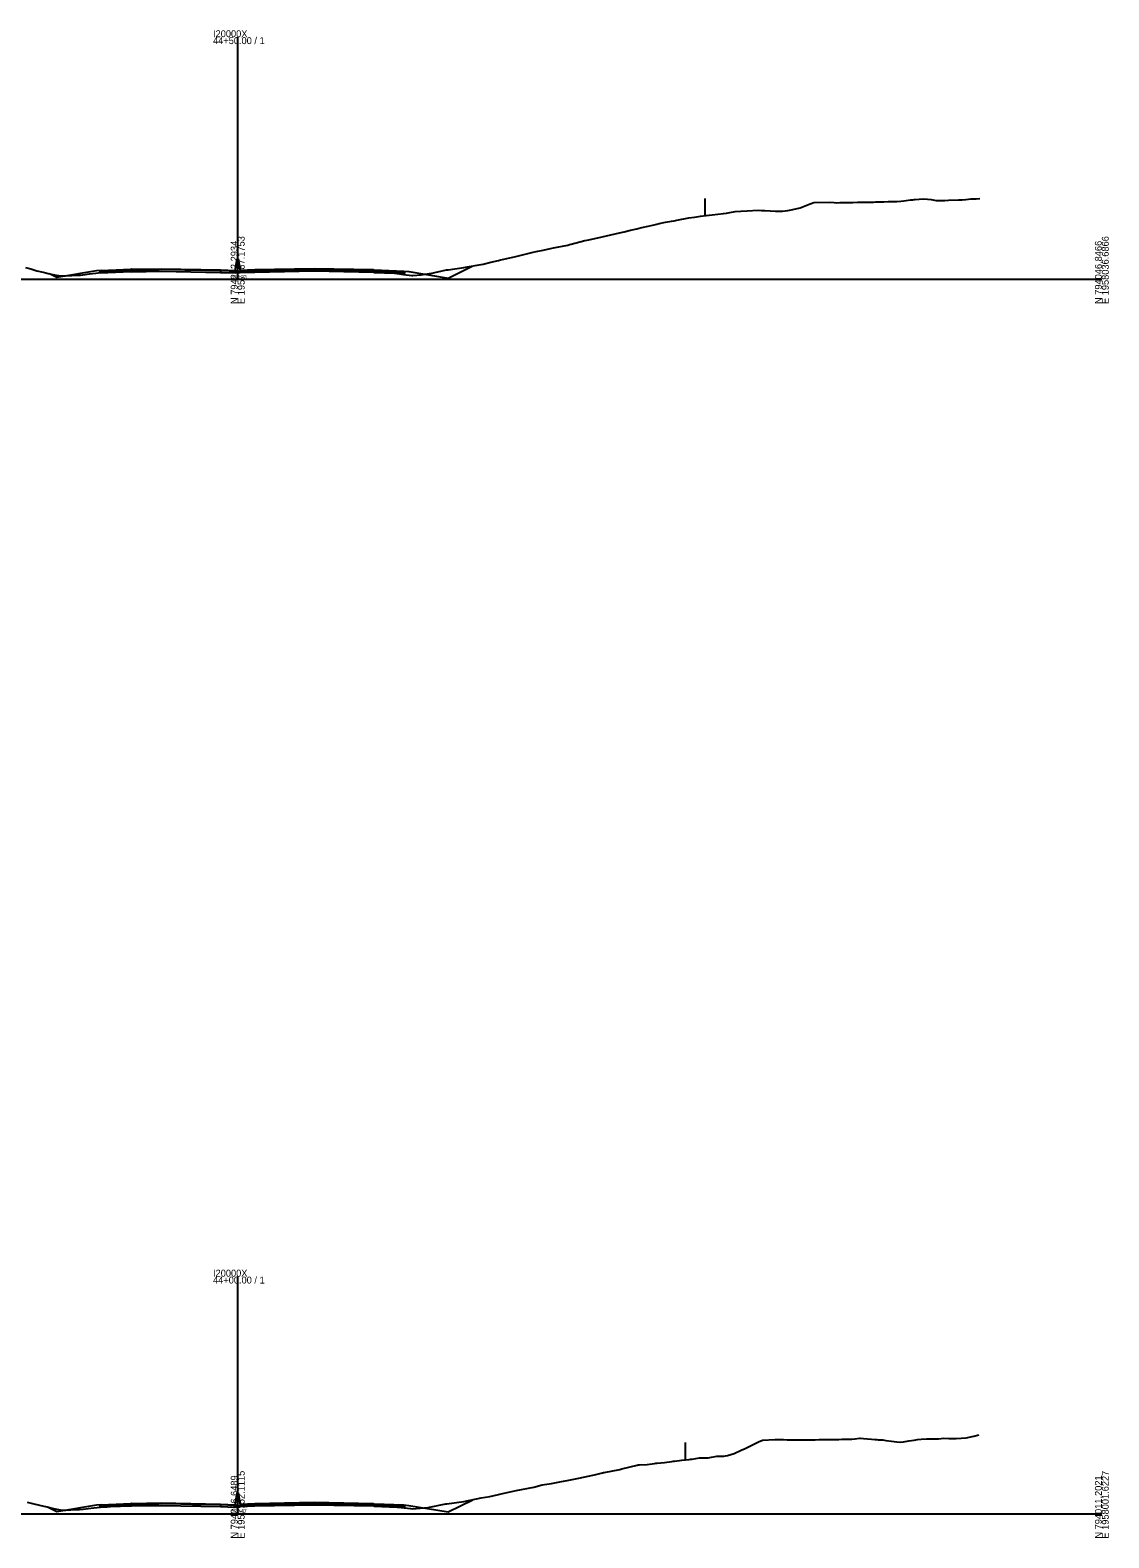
# Model space of a CAD drawing. Extents: x -4026 to 9638, y -10 to 19609.
# Drawn here: x -2734 to -2297, y 13990 to 14601 of the extents above; entities that cross this region are included whole.
import ezdxf

# ---------------------------------------------------------------- set-up
doc = ezdxf.new("R2010")
doc.units = 0
for name, color, linetype in [('RD_EX_Fence_Other', 7, 'Continuous'), ('RD_GPK_XS_Cell', 7, 'Continuous'), ('RD_XS_Base', 7, 'Continuous'), ('RD_XS_ExGround', 7, 'Continuous'), ('RD_XS_Greenside', 7, 'Continuous'), ('RD_XS_MedBWall', 7, 'Continuous'), ('RD_XS_Pave', 7, 'Continuous'), ('RD_XS_PaveOvlay', 7, 'Continuous'), ('RD_XS_TieSlope', 7, 'Continuous'), ('RD_XS_TX_Elev_EX', 7, 'Continuous')]:
    doc.layers.add(name, color=color, linetype=linetype)

msp = doc.modelspace()

# ---------------------------------------------------------------- linework, layer by layer
at = {"layer": 'RD_EX_Fence_Other'}
for p, q in [((-2460.82, 14532.74), (-2460.82, 14525.74)), ((-2468.7, 14028.93), (-2468.7, 14021.93))]:
    msp.add_line(p, q, dxfattribs=at)
at = {"layer": 'RD_GPK_XS_Cell'}
for p, q in [((-2650, 14500), (-2650, 14598.07)), ((-3000, 14500), (-2650, 14500)), ((-2650, 14500), (-2300, 14500)), ((-2650, 14000), (-2650, 14096.1)), ((-3000, 14000), (-2650, 14000)), ((-2650, 14000), (-2300, 14000))]:
    msp.add_line(p, q, dxfattribs=at)
at = {"layer": 'RD_XS_Base'}
for points in [[(-2705.75, 14503.21), (-2705.25, 14503.23), (-2693.25, 14503.71)], [(-2705.75, 14502.54), (-2705.75, 14503.21)], [(-2693.25, 14503.04), (-2705.75, 14502.54)], [(-2693.25, 14503.71), (-2693, 14503.71)], [(-2693.25, 14503.04), (-2693.25, 14503.71)], [(-2693, 14503.04), (-2693.25, 14503.04)], [(-2657, 14503.48), (-2681, 14503.96), (-2693, 14503.71)], [(-2693, 14503.71), (-2693, 14503.04)], [(-2693, 14503.04), (-2681, 14503.29), (-2657, 14502.81)], [(-2651, 14503.24), (-2657, 14503.48)], [(-2657, 14503.48), (-2657, 14502.81)], [(-2657, 14502.81), (-2651, 14502.57)], [(-2651, 14502.57), (-2651, 14503.24)], [(-2649, 14503.26), (-2643, 14503.5)], [(-2649, 14502.59), (-2649, 14503.26)], [(-2643, 14502.83), (-2649, 14502.59)], [(-2643, 14503.5), (-2619, 14503.98), (-2595, 14503.5)], [(-2643, 14502.83), (-2643, 14503.5)], [(-2595, 14502.83), (-2619, 14503.31), (-2643, 14502.83)], [(-2595, 14503.5), (-2594.75, 14503.49)], [(-2595, 14502.83), (-2595, 14503.5)], [(-2594.75, 14502.82), (-2595, 14502.83)], [(-2594.75, 14503.49), (-2594.75, 14502.82)], [(-2582.25, 14502.99), (-2582.75, 14503.01), (-2594.75, 14503.49)], [(-2594.75, 14502.82), (-2582.25, 14502.32)], [(-2582.25, 14502.32), (-2582.25, 14502.99)], [(-2705.75, 14003.38), (-2705.25, 14003.4), (-2693.25, 14003.87)], [(-2705.75, 14002.71), (-2705.75, 14003.38)], [(-2693.25, 14003.2), (-2705.75, 14002.71)], [(-2693.25, 14003.87), (-2693, 14003.88)], [(-2693.25, 14003.2), (-2693.25, 14003.87)], [(-2693, 14003.21), (-2693.25, 14003.2)], [(-2657, 14003.64), (-2681, 14004.12), (-2693, 14003.88)], [(-2693, 14003.88), (-2693, 14003.21)], [(-2693, 14003.21), (-2681, 14003.45), (-2657, 14002.97)], [(-2651, 14003.41), (-2657, 14003.64)], [(-2657, 14003.64), (-2657, 14002.97)], [(-2657, 14002.97), (-2651, 14002.74)], [(-2651, 14002.74), (-2651, 14003.41)], [(-2649, 14003.54), (-2643, 14003.78)], [(-2649, 14002.87), (-2649, 14003.54)], [(-2643, 14003.11), (-2649, 14002.87)], [(-2643, 14003.78), (-2619, 14004.27), (-2595, 14003.78)], [(-2643, 14003.11), (-2643, 14003.78)], [(-2595, 14003.11), (-2619, 14003.6), (-2643, 14003.11)], [(-2595, 14003.78), (-2594.75, 14003.78)], [(-2595, 14003.11), (-2595, 14003.78)], [(-2594.75, 14003.11), (-2595, 14003.11)], [(-2594.75, 14003.78), (-2594.75, 14003.11)], [(-2582.25, 14003.28), (-2582.75, 14003.3), (-2594.75, 14003.78)], [(-2594.75, 14003.11), (-2582.25, 14002.61)], [(-2582.25, 14002.61), (-2582.25, 14003.28)]]:
    msp.add_lwpolyline(points, dxfattribs=at)
at = {"layer": 'RD_XS_ExGround'}
for points in [[(-2735.92, 14504.85), (-2733.78, 14504.25), (-2731.31, 14503.46), (-2728.79, 14502.86), (-2727.77, 14502.61), (-2726.77, 14502.37), (-2724.24, 14501.77), (-2721.66, 14501.47), (-2719.75, 14501.39), (-2714.53, 14501.68), (-2713.63, 14501.75), (-2712.74, 14501.88), (-2710.09, 14502.25), (-2707.4, 14502.53), (-2706.56, 14502.61), (-2704.92, 14502.74), (-2704.35, 14502.79), (-2703.13, 14502.88), (-2699.16, 14503.22), (-2698.77, 14503.24), (-2690.11, 14503.73), (-2689.13, 14503.76), (-2687.92, 14503.81), (-2686.95, 14503.83), (-2686.16, 14503.85), (-2685.51, 14503.86), (-2685.01, 14503.89), (-2678.6, 14504.09), (-2671.98, 14503.92), (-2671.39, 14503.9), (-2670.68, 14503.89), (-2669.83, 14503.87), (-2668.77, 14503.84), (-2667.42, 14503.8), (-2666.86, 14503.79), (-2655.35, 14503.56), (-2649.81, 14503.21), (-2647.63, 14503.21), (-2645.79, 14503.2), (-2643.08, 14503.36), (-2640.65, 14503.5), (-2633.71, 14503.67), (-2628.93, 14503.78), (-2620.18, 14503.96), (-2617.16, 14504.02), (-2616.42, 14504), (-2605.56, 14503.77), (-2598.78, 14503.45), (-2597.14, 14503.38), (-2596.5, 14503.34), (-2589.88, 14502.98), (-2586.2, 14502.49), (-2582.81, 14501.94), (-2579.48, 14501.58), (-2579.07, 14501.58), (-2575.74, 14501.86), (-2572.46, 14502.31), (-2571.94, 14502.41), (-2565.45, 14503.82), (-2565.13, 14503.87), (-2564.81, 14503.9), (-2558.44, 14504.73), (-2557.68, 14504.89), (-2551.42, 14506.02), (-2550.55, 14506.18), (-2547.45, 14506.93), (-2544.41, 14507.69), (-2543.92, 14507.8), (-2543.42, 14507.9), (-2537.4, 14509.24), (-2536.29, 14509.52), (-2530.38, 14510.98), (-2529.16, 14511.25), (-2526.24, 14511.84), (-2523.37, 14512.52), (-2522.03, 14512.82), (-2516.35, 14513.9), (-2515.63, 14514.05), (-2514.9, 14514.25), (-2509.34, 14515.67), (-2507.77, 14516.02), (-2502.33, 14517.24), (-2500.64, 14517.65), (-2495.31, 14518.89), (-2493.51, 14519.28), (-2490.88, 14519.9), (-2488.3, 14520.48), (-2487.35, 14520.72), (-2486.38, 14520.93), (-2483.81, 14521.55), (-2481.29, 14522.09), (-2480.28, 14522.32), (-2479.25, 14522.56), (-2476.74, 14523.1), (-2474.27, 14523.52), (-2473.2, 14523.7), (-2472.12, 14523.94), (-2467.26, 14524.93), (-2464.99, 14525.24), (-2462.6, 14525.58), (-2460.24, 14525.79), (-2459.06, 14526.02), (-2457.86, 14526.11), (-2455.53, 14526.35), (-2453.23, 14526.65), (-2451.99, 14526.81), (-2450.73, 14527.1), (-2448.46, 14527.46), (-2446.22, 14527.56), (-2443.6, 14527.78), (-2439.2, 14528.05), (-2437.85, 14527.91), (-2436.47, 14527.84), (-2434.31, 14527.72), (-2432.19, 14527.67), (-2430.78, 14527.64), (-2429.34, 14527.65), (-2427.24, 14527.82), (-2425.18, 14528.23), (-2422.21, 14529.02), (-2418.16, 14530.52), (-2416.63, 14531.1), (-2410.26, 14531.3), (-2408.37, 14531.12), (-2407.53, 14531.04), (-2406.11, 14531.07), (-2405.71, 14531.07), (-2403.46, 14531.1), (-2402.32, 14531.12), (-2400.79, 14531.15), (-2398.9, 14531.19), (-2398.12, 14531.2), (-2395.29, 14531.23), (-2393.04, 14531.29), (-2392.5, 14531.31), (-2391.61, 14531.33), (-2389.54, 14531.39), (-2388.26, 14531.42), (-2386.57, 14531.46), (-2385.88, 14531.48), (-2383.48, 14531.54), (-2383.05, 14531.55), (-2381.45, 14531.7), (-2380.21, 14531.84), (-2379.19, 14531.95), (-2377.51, 14532.14), (-2376.61, 14532.23), (-2376.04, 14532.29), (-2375.66, 14532.32), (-2372.3, 14532.55), (-2370.67, 14532.51), (-2369.07, 14532.27), (-2367.13, 14531.99), (-2365.17, 14531.87), (-2363.6, 14531.89), (-2362.05, 14532.02), (-2358.04, 14532.16), (-2356.53, 14532.24), (-2355.04, 14532.29), (-2352.99, 14532.56), (-2350.91, 14532.54), (-2349.46, 14532.69)], [(-2735.25, 14004.73), (-2733.69, 14004.38), (-2729.71, 14003.42), (-2726.68, 14002.7), (-2724.65, 14002.22), (-2722.58, 14001.81), (-2721.11, 14001.5), (-2719.66, 14001.53), (-2717.58, 14001.59), (-2715.45, 14001.73), (-2714.04, 14001.83), (-2712.65, 14001.96), (-2710.5, 14002.17), (-2708.32, 14002.41), (-2706.97, 14002.55), (-2704.04, 14002.82), (-2702.9, 14002.92), (-2700.25, 14003.14), (-2699.27, 14003.23), (-2697.24, 14003.36), (-2690.25, 14003.8), (-2689.74, 14003.82), (-2688.4, 14003.86), (-2687.35, 14003.89), (-2686.5, 14003.93), (-2685.8, 14003.95), (-2685.22, 14003.96), (-2678.63, 14004.16), (-2672.3, 14004.07), (-2671.77, 14004.06), (-2671.14, 14004.04), (-2670.39, 14004.04), (-2669.47, 14004.02), (-2668.32, 14004), (-2666.83, 14003.98), (-2655.54, 14003.82), (-2651.54, 14003.56), (-2649.77, 14003.45), (-2648.46, 14003.49), (-2647.48, 14003.51), (-2645.76, 14003.55), (-2643.29, 14003.7), (-2641.58, 14003.79), (-2640.66, 14003.84), (-2629.94, 14004.1), (-2628.97, 14004.12), (-2627.08, 14004.15), (-2617.31, 14004.32), (-2607.02, 14004.14), (-2605.64, 14004.12), (-2604.53, 14004.07), (-2596.99, 14003.75), (-2596.39, 14003.74), (-2590.29, 14003.52), (-2587.12, 14003.02), (-2586.4, 14002.91), (-2579.99, 14002.14), (-2579.39, 14002.12), (-2572.86, 14002.6), (-2572.37, 14002.68), (-2565.73, 14004.03), (-2565.36, 14004.12), (-2558.35, 14005.01), (-2551.33, 14006.51), (-2547.86, 14007.09), (-2544.32, 14007.86), (-2543.25, 14008.11), (-2537.21, 14009.51), (-2530.08, 14010.83), (-2526.65, 14011.71), (-2522.95, 14012.27), (-2519.58, 14012.94), (-2515.82, 14013.68), (-2512.51, 14014.4), (-2509.25, 14015.06), (-2508.69, 14015.18), (-2505.44, 14015.78), (-2502.24, 14016.65), (-2501.9, 14016.73), (-2501.56, 14016.81), (-2495.22, 14018.03), (-2494.83, 14018.1), (-2494.43, 14018.21), (-2488.21, 14019.71), (-2487.76, 14019.81), (-2487.3, 14019.85), (-2484.22, 14020.07), (-2481.2, 14020.46), (-2480.69, 14020.53), (-2480.17, 14020.56), (-2477.15, 14020.87), (-2474.18, 14021.23), (-2473.62, 14021.3), (-2473.04, 14021.4), (-2470.08, 14021.82), (-2467.17, 14022.06), (-2466.54, 14022.11), (-2465.91, 14022.19), (-2463.01, 14022.68), (-2460.15, 14022.66), (-2459.47, 14022.7), (-2458.78, 14022.79), (-2455.94, 14023.42), (-2453.14, 14023.45), (-2452.4, 14023.53), (-2451.65, 14023.64), (-2448.87, 14024.43), (-2446.13, 14025.8), (-2444.52, 14026.52), (-2439.11, 14029.18), (-2437.39, 14029.85), (-2432.4, 14030.16), (-2431.71, 14030.14), (-2430.64, 14030.11), (-2428.98, 14030.09), (-2427.42, 14030.02), (-2426.5, 14029.97), (-2425.27, 14029.98), (-2422.93, 14030.01), (-2421.94, 14030.01), (-2420.3, 14030.02), (-2418.58, 14030.04), (-2417.69, 14030.05), (-2416.53, 14030.05), (-2416.12, 14030.05), (-2414.48, 14030.08), (-2413.59, 14030.1), (-2411.36, 14030.13), (-2410.68, 14030.14), (-2408.97, 14030.16), (-2407.75, 14030.18), (-2406.58, 14030.19), (-2405.33, 14030.21), (-2404.63, 14030.22), (-2402.59, 14030.25), (-2401.25, 14030.28), (-2399.93, 14030.45), (-2398.17, 14030.66), (-2397.72, 14030.63), (-2396.6, 14030.57), (-2393.3, 14030.26), (-2391.94, 14030.14), (-2391.16, 14030.08), (-2390.65, 14030.04), (-2388.76, 14029.94), (-2387.48, 14029.76), (-2385.22, 14029.43), (-2383, 14029.15), (-2381.69, 14029), (-2380.35, 14029.16), (-2378.15, 14029.62), (-2375.99, 14029.93), (-2374.62, 14030.11), (-2373.22, 14030.26), (-2371.08, 14030.35), (-2368.98, 14030.34), (-2367.55, 14030.35), (-2366.09, 14030.43), (-2364.01, 14030.66), (-2361.96, 14030.54), (-2360.47, 14030.52), (-2358.96, 14030.56), (-2356.94, 14030.69), (-2354.95, 14030.83), (-2351.83, 14031.55), (-2349.87, 14032.03)]]:
    msp.add_lwpolyline(points, dxfattribs=at)
at = {"layer": 'RD_XS_Greenside'}
for points in [[(-2707.25, 14503.41), (-2723.25, 14500.74)], [(-2705.25, 14503.57), (-2707.25, 14503.41)], [(-2582.75, 14503.35), (-2580.75, 14503.18)], [(-2580.75, 14503.18), (-2564.75, 14500.51)], [(-2707.25, 14003.57), (-2723.25, 14000.9)], [(-2705.25, 14003.73), (-2707.25, 14003.57)], [(-2582.75, 14003.64), (-2580.75, 14003.47)], [(-2580.75, 14003.47), (-2564.75, 14000.8)]]:
    msp.add_lwpolyline(points, dxfattribs=at)
at = {"layer": 'RD_XS_MedBWall'}
for points in [[(-2651, 14503.57), (-2650.25, 14508.25), (-2649.75, 14508.25), (-2649, 14503.58)], [(-2651, 14502.57), (-2651, 14503.57)], [(-2649, 14502.57), (-2651, 14502.57)], [(-2649, 14503.58), (-2649, 14502.57)], [(-2651, 14003.74), (-2650.25, 14008.54), (-2649.75, 14008.54), (-2649, 14003.87)], [(-2651, 14002.74), (-2651, 14003.74)], [(-2649, 14002.74), (-2651, 14002.74)], [(-2649, 14003.87), (-2649, 14002.74)]]:
    msp.add_lwpolyline(points, dxfattribs=at)
at = {"layer": 'RD_XS_Pave'}
for points in [[(-2705.25, 14503.4), (-2693.25, 14503.88)], [(-2693.25, 14503.71), (-2705.25, 14503.23)], [(-2705.25, 14503.23), (-2705.25, 14503.4)], [(-2693.25, 14503.88), (-2693, 14503.88)], [(-2693.25, 14503.71), (-2693.25, 14503.88)], [(-2693, 14503.71), (-2693.25, 14503.71)], [(-2693, 14503.88), (-2681, 14504.13), (-2657, 14503.65)], [(-2657, 14503.48), (-2681, 14503.96), (-2693, 14503.71)], [(-2693, 14503.88), (-2693, 14503.71)], [(-2657, 14503.65), (-2657, 14503.48)], [(-2657, 14503.65), (-2651, 14503.41)], [(-2651, 14503.24), (-2657, 14503.48)], [(-2651, 14503.41), (-2651, 14503.24)], [(-2643, 14503.67), (-2649, 14503.43)], [(-2649, 14503.26), (-2643, 14503.5)], [(-2649, 14503.43), (-2649, 14503.26)], [(-2595, 14503.67), (-2619, 14504.15), (-2643, 14503.67)], [(-2643, 14503.5), (-2619, 14503.98), (-2595, 14503.5)], [(-2643, 14503.67), (-2643, 14503.5)], [(-2595, 14503.67), (-2594.75, 14503.66)], [(-2595, 14503.5), (-2595, 14503.67)], [(-2594.75, 14503.49), (-2595, 14503.5)], [(-2594.75, 14503.66), (-2594.75, 14503.49)], [(-2582.75, 14503.18), (-2594.75, 14503.66)], [(-2594.75, 14503.49), (-2582.75, 14503.01)], [(-2582.75, 14503.01), (-2582.75, 14503.18)], [(-2705.25, 14003.56), (-2693.25, 14004.04)], [(-2693.25, 14003.87), (-2705.25, 14003.4)], [(-2705.25, 14003.4), (-2705.25, 14003.56)], [(-2693.25, 14004.04), (-2693, 14004.05)], [(-2693.25, 14003.87), (-2693.25, 14004.04)], [(-2693, 14003.88), (-2693.25, 14003.87)], [(-2693, 14004.05), (-2681, 14004.29), (-2657, 14003.81)], [(-2657, 14003.64), (-2681, 14004.12), (-2693, 14003.88)], [(-2693, 14004.05), (-2693, 14003.88)], [(-2657, 14003.81), (-2657, 14003.64)], [(-2657, 14003.81), (-2651, 14003.58)], [(-2651, 14003.41), (-2657, 14003.64)], [(-2651, 14003.58), (-2651, 14003.41)], [(-2643, 14003.95), (-2649, 14003.71)], [(-2649, 14003.54), (-2643, 14003.78)], [(-2649, 14003.71), (-2649, 14003.54)], [(-2595, 14003.95), (-2619, 14004.43), (-2643, 14003.95)], [(-2643, 14003.78), (-2619, 14004.27), (-2595, 14003.78)], [(-2643, 14003.95), (-2643, 14003.78)], [(-2595, 14003.95), (-2594.75, 14003.95)], [(-2595, 14003.78), (-2595, 14003.95)], [(-2594.75, 14003.78), (-2595, 14003.78)], [(-2594.75, 14003.95), (-2594.75, 14003.78)], [(-2582.75, 14003.47), (-2594.75, 14003.95)], [(-2594.75, 14003.78), (-2582.75, 14003.3)], [(-2582.75, 14003.3), (-2582.75, 14003.47)]]:
    msp.add_lwpolyline(points, dxfattribs=at)
at = {"layer": 'RD_XS_PaveOvlay'}
for points in [[(-2705.25, 14503.57), (-2693.25, 14504.05)], [(-2693.25, 14503.88), (-2705.25, 14503.4)], [(-2705.25, 14503.4), (-2705.25, 14503.57)], [(-2693.25, 14504.05), (-2693.25, 14503.88)], [(-2693, 14504.05), (-2693.25, 14504.05)], [(-2693.25, 14503.88), (-2693, 14503.88)], [(-2693, 14504.05), (-2681, 14504.29), (-2657, 14503.81)], [(-2657, 14503.65), (-2681, 14504.13), (-2693, 14503.88)], [(-2693, 14503.88), (-2693, 14504.05)], [(-2657, 14503.81), (-2657, 14503.65)], [(-2657, 14503.81), (-2651, 14503.57)], [(-2651, 14503.41), (-2657, 14503.65)], [(-2651, 14503.57), (-2651, 14503.41)], [(-2643, 14503.83), (-2649, 14503.58)], [(-2649, 14503.43), (-2643, 14503.67)], [(-2649, 14503.58), (-2649, 14503.43)], [(-2595, 14503.83), (-2619, 14504.31), (-2643, 14503.83)], [(-2643, 14503.67), (-2619, 14504.15), (-2595, 14503.67)], [(-2643, 14503.83), (-2643, 14503.67)], [(-2595, 14503.67), (-2595, 14503.83)], [(-2595, 14503.83), (-2594.75, 14503.83)], [(-2594.75, 14503.66), (-2595, 14503.67)], [(-2594.75, 14503.83), (-2594.75, 14503.66)], [(-2594.75, 14503.83), (-2582.75, 14503.35)], [(-2582.75, 14503.18), (-2594.75, 14503.66)], [(-2582.75, 14503.35), (-2582.75, 14503.18)], [(-2705.25, 14003.73), (-2693.25, 14004.21)], [(-2693.25, 14004.04), (-2705.25, 14003.56)], [(-2705.25, 14003.56), (-2705.25, 14003.73)], [(-2693, 14004.22), (-2693.25, 14004.21)], [(-2693.25, 14004.21), (-2693.25, 14004.04)], [(-2693.25, 14004.04), (-2693, 14004.05)], [(-2693, 14004.22), (-2681, 14004.46), (-2657, 14003.98)], [(-2657, 14003.81), (-2681, 14004.29), (-2693, 14004.05)], [(-2693, 14004.05), (-2693, 14004.22)], [(-2657, 14003.98), (-2657, 14003.81)], [(-2657, 14003.98), (-2651, 14003.74)], [(-2651, 14003.58), (-2657, 14003.81)], [(-2651, 14003.74), (-2651, 14003.58)], [(-2643, 14004.12), (-2649, 14003.87)], [(-2649, 14003.71), (-2643, 14003.95)], [(-2649, 14003.87), (-2649, 14003.71)], [(-2595, 14004.12), (-2619, 14004.6), (-2643, 14004.12)], [(-2643, 14003.95), (-2619, 14004.43), (-2595, 14003.95)], [(-2643, 14004.12), (-2643, 14003.95)], [(-2595, 14003.95), (-2595, 14004.12)], [(-2595, 14004.12), (-2594.75, 14004.12)], [(-2594.75, 14003.95), (-2595, 14003.95)], [(-2594.75, 14004.12), (-2594.75, 14003.95)], [(-2594.75, 14004.12), (-2582.75, 14003.64)], [(-2582.75, 14003.47), (-2594.75, 14003.95)], [(-2582.75, 14003.64), (-2582.75, 14003.47)]]:
    msp.add_lwpolyline(points, dxfattribs=at)
at = {"layer": 'RD_XS_TieSlope'}
for points in [[(-2723.25, 14500.74), (-2726.29, 14502.26)], [(-2564.75, 14500.51), (-2555.05, 14505.37)], [(-2723.25, 14000.9), (-2727, 14002.78)], [(-2564.75, 14000.8), (-2554.83, 14005.76)]]:
    msp.add_lwpolyline(points, dxfattribs=at)

# ---------------------------------------------------------------- texts
at = {"layer": 'RD_GPK_XS_Cell'}
for s, p in [('I20000X', (-2660, 14598.07)), ('44+50.00 / 1', (-2660, 14595.27)), ('44+00.00 / 1', (-2660, 14093.3)), ('I20000X', (-2660, 14096.1))]:
    msp.add_text(s, height=2.8, dxfattribs=at).set_placement(p)
for s, p in [('N 794292.2934', (-2650, 14490)), ('E 1957787.1753', (-2647.2, 14490)), ('N 794046.8466', (-2300, 14490)), ('E 1958036.6866', (-2297.2, 14490)), ('N 794256.6489', (-2650, 13990)), ('E 1957752.1115', (-2647.2, 13990)), ('N 794011.2021', (-2300, 13990)), ('E 1958001.6227', (-2297.2, 13990))]:
    msp.add_text(s, height=2.8, rotation=90, dxfattribs=at).set_placement(p)
at = {"layer": 'RD_XS_TX_Elev_EX'}
for s, p in [('323.23', (-2652.69, 14500.23)), ('323.47', (-2652.68, 14000.47))]:
    msp.add_text(s, height=1.5, dxfattribs=at).set_placement(p)

doc.saveas('drawing.dxf')
